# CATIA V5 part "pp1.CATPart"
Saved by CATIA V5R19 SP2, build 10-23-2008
Part number: pp1
Publications: "Point.1", "Point.2", "Point.3", "Point.4", "yz plane", "Point.5", "Point.6", "Point.7", "Point.8", "Point.11", "Point.12", "Point.13", "Point.14"
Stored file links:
  C:\Users\Welcome\Documents\thinkm2\pp1.CATPart
  C:\Users\Welcome\Documents\thinkm2\pp8copy.CATPart

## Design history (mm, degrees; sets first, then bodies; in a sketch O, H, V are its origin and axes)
AxisSystem1: origin (0, 0, 0), X (1, 0, 0), Y (0, 1, 0), Z (0, 0, 1)
Body1 (main body)
  Point1: (0, 100, 50), in AxisSystem1
  Point2: (0, -100, 50), in AxisSystem1
  Point3: (0, -100, -50), in AxisSystem1
  Point4: (0, 100, -50), in AxisSystem1
  Point5: (0, -130, 25), in AxisSystem1
  Point6: (0, -130, -25), in AxisSystem1
  Point7: (0, -190, 25), in AxisSystem1
  Point8: (0, -190, -25), in AxisSystem1
  Point9: (0, -220, 50), in AxisSystem1
  Point10: (0, -220, -50), in AxisSystem1
  Point11: (0, -420, -50), in AxisSystem1
  Point12: (0, -420, 50), in AxisSystem1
